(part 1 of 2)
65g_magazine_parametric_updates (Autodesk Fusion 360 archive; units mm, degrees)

design "65g_magazine_parametric_updates" references "65_g_floorplate"
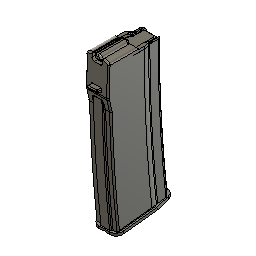
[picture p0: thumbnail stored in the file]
parameter "CartrigeOAL" = 57.9
parameter "magazineShoulder" = 35.6
parameter "feedLipRadius" = 5.6
parameter "primaryWallThickness" = 2
parameter "feedliplength" = 29.6
parameter "frontWidth" = 16
parameter "rearwidth" = 22
parameter "addtlfeedlipthickness" = 3.5
parameter "bananaFactor" = 1509
parameter "floorplateclearance" = 2
parameter "followerOffset" = -0.75
parameter "d1137" = 350
parameter "d372" = 1
parameter "d374" = 0.7
parameter "d376" = 0.7
parameter "d377" = -1
parameter "d378" = 0
parameter "d380" = 0.5
parameter "d387" = 7
parameter "d389" = 1
parameter "d390" = 4
parameter "d391" = 0.75
parameter "d392" = -9
parameter "d393" = 0
parameter "d394" = 10
parameter "d400" = 10
parameter "d401" = 5
parameter "d402" = -0.5
parameter "d403" = 0
parameter "d404" = 0
parameter "d405" = 0
parameter "d406" = 4
parameter "d407" = 3
parameter "d408" = 3
parameter "d409" = 0
parameter "d411" = 1
parameter "d412" = 17
parameter "d413" = 1.5
parameter "d415" = 3
parameter "d418" = 6
parameter "d419" = 1.5
parameter "d420" = 2.5
parameter "d421" = 0
parameter "d423" = 2
parameter "d425" = 0.5
base_feature "Base Feature1" bodies "follower", "mag body", "feed geometry", "random cube", "placeholder to establish center"
derived_base_feature "Derived Base Feature2" bodies "main body", "updated lock lug", "template lock lug from m76"
remove_body "RemoveBody1"
sketch "top down profile" plane through (0, 0, 0) normal (0, 1, 0) x axis (1, 0, 0)
  line L1 (-11, 0) -> (0, 0)
  line L2 (0, 57.9) -> (0, 0)
  line L3 (-11, 35.6) -> (-11, 0)
  line L4 (-8, 44.9274) -> (-8, 53.9)
  line L5 (-4, 57.9) -> (0, 57.9)
  line L6 (-4, 57.9) -> (0, 57.9)
  line L7 (0, 57.9) -> (0, 0)
  line L8 (11, 35.6) -> (11, 0)
  line L9 (8, 44.9274) -> (8, 53.9)
  line L10 (4, 57.9) -> (0, 57.9)
  line L11 (11, 0) -> (0, 0)
  line L12 (-13, -2) -> (0, -2)
  line L13 (-4.2574, 61.8) -> (0, 61.8)
  line L14 (-13, 37) -> (-13, -2)
  line L15 (-6.3787, 60.9213) -> (-10.1219, 57.1781)
  line L16 (6.3787, 60.9213) -> (10.1219, 57.1781)
  line L17 (13, 37) -> (13, -2)
  line L18 (13, -2) -> (0, -2)
  line L19 (4.2574, 61.8) -> (0, 61.8)
  line L20 (-11, 27.6) -> (-13, 27.6)
  line L21 (-11, -2) -> (-11, 0)
  line L22 (-9.4578, 32.9452) -> (-8.5625, 43.1785)
  line L23 (0.2269, 43.1785) -> (-8.5625, 43.1785)
  line L24 (-9.9889, 31.486) -> (-11, 30.042)
  line L25 (-11.7322, 43.1785) -> (-8.5625, 43.1785)
  line L26 (-11, 49.3) -> (-8, 49.3)
  line L27 (-30.8129, 55.0827) -> (-11, 55)
  line L28 (-30.9385, 25) -> (-30.8129, 55.0827)
  line L29 (-13, 25) -> (-30.9385, 25)
  line L30 (-11, 45.4853) -> (-11, 55)
  line L31 (11, 45.4853) -> (11, 55)
  line L32 (-6, -4) -> (6, -4)
  line L33 (6, -2) -> (6, -4)
  line L34 (-6, -2) -> (-6, -4)
  arc A1 centre (-4, 53.9) radius 4 clockwise from (-8, 53.9) to (-4, 57.9)
  arc A2 centre (2, 35.6) radius 13 clockwise from (-11, 35.6) to (-8.5625, 43.1785)
  arc A3 centre (-11, 44.9274) radius 3 clockwise from (-8, 44.9274) to (-8.5625, 43.1785)
  arc A4 centre (-2, 35.6) radius 13 clockwise from (8.5625, 43.1785) to (11, 35.6)
  arc A5 centre (11, 44.9274) radius 3 clockwise from (8.5625, 43.1785) to (8, 44.9274)
  arc A6 centre (4, 53.9) radius 4 clockwise from (4, 57.9) to (8, 53.9)
  arc A7 centre (2, 37) radius 15 clockwise from (-13, 37) to (-11.4211, 43.6989)
  arc A8 centre (-15, 45.4853) radius 4 clockwise from (-11, 45.4853) to (-11.4211, 43.6989)
  arc A9 centre (-8.0005, 55.0568) radius 3 clockwise from (-11, 55) to (-10.1219, 57.1781)
  arc A10 centre (-4.2574, 58.8) radius 3 clockwise from (-6.3787, 60.9213) to (-4.2574, 61.8)
  arc A11 centre (4.2574, 58.8) radius 3 clockwise from (4.2574, 61.8) to (6.3787, 60.9213)
  arc A12 centre (8.0005, 55.0568) radius 3 clockwise from (10.1219, 57.1781) to (11, 55)
  arc A13 centre (15, 45.4853) radius 4 clockwise from (11.4211, 43.6989) to (11, 45.4853)
  arc A14 centre (-2, 37) radius 15 clockwise from (11.4211, 43.6989) to (13, 37)
  arc A15 centre (-12.4464, 33.2067) radius 3 clockwise from (-9.4578, 32.9452) to (-9.9889, 31.486)
  circle C1 centre (-10.808, 41.9164) radius 1.2808
  point P1 (0, 0)
  point P2 (0, 0)
  point P4 (0, 0)
  point P25 (0, 0)
  point P3 (-11, 0)
  point P16 (11, 0)
  point P14 (0, 0)
  point P5 (0, 57.9)
  point P15 (0, 57.9)
  point P7 (-4, 57.9)
  point P24 (4, 57.9)
  point P8 (-8, 53.9)
  point P22 (8, 53.9)
  point P10 (-11, 35.6)
  point P17 (11, 35.6)
  point P12 (-8, 44.9274)
  point P21 (8, 44.9274)
  point P13 (-8.5625, 43.1785)
  point P19 (8.5625, 43.1785)
  point P33 (-5.5, 61.8)
  point P26 (0, -2)
  point P52 (0, -2)
  point P27 (-13, -2)
  point P51 (13, -2)
  point P28 (-13, 37)
  point P50 (13, 37)
  point P30 (-11, 45.4853)
  point P46 (11, 45.4853)
  point P31 (-11.4211, 43.6989)
  point P48 (11.4211, 43.6989)
  point P34 (-10.1219, 57.1781)
  point P43 (10.1219, 57.1781)
  point P35 (-11, 55)
  point P45 (11, 55)
  point P37 (-6.3787, 60.9213)
  point P42 (6.3787, 60.9213)
  point P38 (-4.2574, 61.8)
  point P41 (4.2574, 61.8)
  point P54 (-13, 27.6)
  point P55 (-11, 27.6)
  point P56 (-11, -2)
  point P58 (-11, 30.042)
  point P62 (-11.7322, 43.1785)
  point P63 (-8, 49.3)
  point P67 (-13, 25)
  point P70 (6, -2)
  point P71 (-6, -2)
  point P68 (6, -4)
  point P69 (-6, -4)
  point P72 (-10.808, 41.9164)
  coincident P1 P2
  horizontal L1
  coincident P1 P4
  perpendicular L1 L2
  perpendicular L1 L3
  perpendicular L1 L4
  perpendicular L2 L5
  tangent L5 A1
  tangent L4 A1
  tangent L6 A1
  tangent L3 A2
  tangent A2 A3
  tangent L4 A3
  symmetric P2 L2 P25
  symmetric P3 L2 P16
  symmetric P4 L2 P14
  symmetric P5 L2 P15
  symmetric L2 P7 P24
  symmetric L2 A1 A6
  symmetric L2 P8 P22
  symmetric L2 P10 P17
  symmetric L2 A2 A4
  symmetric L2 P12 P21
  symmetric L2 P13 P19
  symmetric L2 A3 A5
  horizontal L12
  horizontal L13
  perpendicular L12 L14
  tangent L14 A7
  tangent A7 A8
  tangent L15 A9
  coincident P33 L15
  coincident L13 P33
  tangent L15 A10
  tangent L13 A10
  equal A9 A10
  symmetric L2 P26 P52
  symmetric L2 P27 P51
  symmetric L2 P28 P50
  symmetric L2 A7 A14
  symmetric L2 P30 P46
  symmetric L2 P31 P48
  symmetric L2 A8 A13
  symmetric L2 P34 P43
  symmetric L2 P35 P45
  symmetric L2 A9 A12
  symmetric L2 P37 P42
  symmetric L2 P38 P41
  symmetric L2 A10 A11
  coincident L14 P54
  coincident L3 P55
  perpendicular L3 L20
  coincident L12 P56
  perpendicular L12 L21
  horizontal L23
  coincident L3 P58
  tangent L22 A15
  tangent L24 A15
  horizontal L25
  coincident A8 P62
  coincident L4 P63
  perpendicular L27 L28
  coincident L14 P67
  perpendicular L14 L29
  tangent A8 L30
  vertical L30
  parallel L11 L32
  coincident L18 P70
  perpendicular L18 L33
  coincident L12 P71
  perpendicular L12 L34
  tangent A2 C1
  tangent A7 C1
  dimension "d571" distance P2 P3 = 11 (= "rearwidth / 2")
  dimension "d572" distance P4 P5 = 57.9 (= "CartrigeOAL")
  dimension "d573" distance P5 L4 = 8 (= "frontWidth / 2")
  dimension "d574" diameter A1 = 8
  dimension "d577" diameter A3 = 6
  dimension "d578" distance P26 P27 = 13 (= "d571 + 2 mm")
  dimension "d579" distance L1 L12 = 2 (= "primaryWallThickness")
  dimension "d580" distance L12 L13 = 63.8 (= "d572 + 5.9 mm")
  dimension "d586" radius A8 = 4
  dimension "d590" radius A9 = 3
  dimension "d591" angle L13 L15 = 135
  dimension "d601" distance L12 L20 = 29.6 (= "feedliplength")
  dimension "d618" angle L22 L23 = 95
  dimension "d622" radius A15 = 3
  dimension "d623" angle L3 L24 = 145
  dimension "d679" distance L13 L26 = 12.5
  dimension "d681" distance L13 P35 = 6.8
  dimension "d683" distance L3 L14 = 2 (= "d579")
  dimension "d685" distance P3 P10 = 35.6 (= "magazineShoulder")
  dimension "d686" distance L1 P28 = 37 (= "d685 + 1.4 mm")
  dimension "d699" distance P58 L25 = 13.1365
  dimension "d700" distance L7 L30 = 11 (= "d573 + 3 mm")
  dimension "d754" distance P68 P69 = 12
  dimension "d755" distance L7 P68 = 6 (= "d754 / 2")
  dimension "d756" distance L18 L32 = 2
  dimension "d779" diameter C1 = 2.5616
  dimension "d780" distance P30 P72 = 3.5688
sketch "Sketch4" plane through (0, 0, 0) normal (0, 1, 0) x axis (1, 0, 0)
  line L1 (2.35, 53.733) -> (2.35, 46.32)
  line L2 (2.35, 53.733) -> (2.35, 52.4025)
  line L3 (2.35, 48.3729) -> (2.35, 52.4025)
  line L4 (2.35, 45) -> (2.35, 48.3729)
  line L5 (2.35, 46.32) -> (2.35, 45)
  curve K1 (1.7875, 44.5687) -> (-0.65, 36.9798)
  line L6 (1.7875, 44.5687) -> (1.7875, 43.2511)
  line L7 (-0.65, 36.9798) -> (-0.65, 35.6726)
  line L8 (-0.65, 36.9798) -> (-0.65, 1.2627)
  line L9 (-0.65, 36.9798) -> (-0.65, 35.6726)
  line L10 (-0.65, 29.2298) -> (-0.65, 35.6726)
  line L11 (-0.65, 0.0025) -> (-0.65, 29.2298)
  line L12 (-0.65, 0.0025) -> (-0.65, 1.2627)
  curve K2 (2.35, 46.32) -> (1.7875, 44.5687)
  line L13 (2.35, 46.32) -> (2.35, 45)
  line L14 (1.7875, 44.5687) -> (1.7875, 43.2511)
  line L15 (0.8031, 31.5304) -> (1.7875, 43.2511)
  line L16 (-0.65, 29.2298) -> (0.3422, 30.4123)
  arc A1 centre (-1.1899, 31.6978) radius 2 clockwise from (0.8031, 31.5304) to (0.3422, 30.4123)
sketch "Banana Factor" plane through (0, 0, 0) normal (1, 0, 0) x axis (0, 1, 0)
  line L1 (0, -57.9) -> (0, 0)
  line L2 (0, -35.6) -> (0, 0)
  line L3 (0, -35.6) -> (0, -43.1785)
  line L4 (0, -43.1785) -> (0, -44.9274)
  line L5 (0, -44.9274) -> (0, -53.9)
  line L6 (0, -53.9) -> (0, -57.9)
  line L7 (0, -57.9) -> (0, 0)
  line L8 (0, -35.6) -> (0, 0)
  line L9 (0, -35.6) -> (0, -43.1785)
  line L10 (0, -43.1785) -> (0, -44.9274)
  line L11 (0, -44.9274) -> (0, -53.9)
  line L12 (0, -53.9) -> (0, -57.9)
  line L13 (0, -29.227) -> (0, 0)
  line L14 (0, -1538.227) -> (0, -29.227)
  circle C1 centre (0, -1538.227) radius 1509
  point P12 (0, 0)
  point P22 (0, 0)
  point P24 (0, -1538.227)
  point P25 (0, -1538.227)
  point P23 (0, -29.227)
  coincident P12 P22
  parallel L2 L13
  parallel L5 L14
  coincident P24 P25
  coincident P23 C1
  dimension "d593" distance P22 P23 = 29.227
  dimension "d594" distance P23 P24 = 1509 (= "bananaFactor")
sweep "Sweep1" sketch "top down profile" TwistAngle 0 TaperAngle 0
sketch "feed lip curvature/radius" plane through (0, 0, 0) normal (0, 0, 1) x axis (1, 0, 0)
  line L1 (-5.4, 0) -> (-11, 0)
  line L2 (-5.4, 5.6) -> (-5.4, 0)
  curve K1 (0.2, 3.5) -> (-11, 3.5)
  curve K2 (-5.4, 5.5588) -> (-5.4, 1.4412)
  curve K3 (-5.4, 6.6) -> (-5.4, -6.6)
  curve K4 (-11, 0) -> (0.2, 0)
  line L3 (0.7, 0) -> (-5.4, 0)
  circle C1 centre (-5.4, 0) radius 5.6
  closed curve K5 centre (-5.4, 3.5)
  closed curve K6 centre (-5.4, 0)
  point P2 (-11, 0)
  point P3 (-11, 0)
  point P4 (-5.4, 0)
  point P5 (-5.4, 0)
  point P6 (-5.4, 5.6)
  point P8 (-11, 3.5)
  point P9 (0.2, 3.5)
  point P10 (-5.4, 1.4412)
  point P11 (-5.4, 5.5588)
  point P13 (-5.4, -6.6)
  point P14 (-5.4, 6.6)
  point P15 (0.2, 0)
  point P16 (-11, 0)
  point P7 (-5.4, 3.5)
  coincident P2 P3
  horizontal L1
  coincident P4 P5
  coincident P2 C1
  coincident C1 P6
  perpendicular L1 L2
  coincident K5 P8
  coincident K5 P9
  coincident K5 P10
  coincident K5 P11
  horizontal K1
  collinear L2 K2
  coincident L2 P11
  coincident K6 P13
  coincident K6 P14
  coincident K6 P15
  coincident K6 P16
  concentric C1 K6
  coincident P3 P16
  horizontal L3
  dimension "d602" distance P3 P4 = 5.6 (= "feedLipRadius")
  dimension "d730" distance K5 = 11.2 (= "feedLipRadius * 2")
  dimension "d731" distance P5 K1 = 3.5 (= "addtlfeedlipthickness")
  dimension "d746" = 4.1176 (= "d747 * 2 / 1.02")
  dimension "d747" distance P6 P7 = 2.1
  dimension "d1105" distance K6 = 13.2
sweep "Sweep2" sketch "top down profile" TwistAngle 0 TaperAngle 0 bodies "feed lip"
extrude "Extrude2" new body sketch "top down profile" profile of L3 L12 L14 L20 L21 along normal blind 3.5 (= "addtlfeedlipthickness")
sweep "Sweep1" TwistAngle 0 TaperAngle -0.8
extrude "Extrude9" new body sketch "top down profile" profile of L3 L12 L14 L20 L21 along normal blind 3.5 (= "addtlfeedlipthickness")
sweep "Sweep5" TwistAngle 0 TaperAngle 0
move "Move1"
extrude "Extrude17" cut sketch "feed lip curvature/radius" profile of C1 K5 K6 to an object Side2Offset 0
sketch "feed lip fill in" plane through (0, 0, 2) normal (0, 0, 1) x axis (1, 0, 0)
  line L1 (-11, 0) -> (-13, 0)
  line L2 (-6.3525, 7.5401) -> (-6.2247, 6.528)
  line L3 (-6.2247, 0) -> (-6.2247, 6.528)
  line L4 (-13, 0) -> (0, 0)
  line L5 (-13, 0) -> (-13, 3.5)
  line L6 (-6.575, 7.5184) -> (-6.5744, 7.5087)
  curve K1 (-6.575, 7.5184) -> (-13, 3.5)
  line L7 (-6.5751, 12.5087) -> (-6.5744, 7.5087)
  line L8 (-18, 0) -> (-13, 0)
  line L9 (-18, 12.7693) -> (-18, 0)
  line L10 (-6.5751, 12.5087) -> (-18, 12.7693)
  arc A1 centre (-5.4, 0) radius 7.6 clockwise from (-6.5744, 7.5087) to (-6.3525, 7.5401)
  closed curve K2 centre (-5.4, 0)
  point P4 (-6.2247, 6.528)
  point P7 (-6.2247, 6.528)
  point P8 (-6.2247, 0)
  point P2 (-6.5744, 7.5087)
  point P14 (-6.5744, 7.5087)
  point P11 (-13, 0)
  point P16 (-13, 0)
  point P15 (-6.5751, 12.5087)
  point P17 (-18, 0)
  coincident P4 P7
  coincident P8 L4
  perpendicular L3 L4
  coincident P2 P14
  coincident P11 P16
  perpendicular L5 L8
  perpendicular L8 L9
  dimension "d1089" distance P14 P15 = 5
  dimension "d1090" distance P16 P17 = 5
extrude "Extrude1" add sketch "feed lip fill in" profile of L4 L3 against normal blind 2
sketch "Draft pull tool" plane through (0, 0, 0) normal (0, 0, 1) x axis (1, 0, 0)
  line L1 (-6.2247, 6.528) -> (-6.3525, 7.5401)
  line L2 (-14.3525, 7.5401) -> (-6.3525, 7.5401)
  line L3 (-14.3525, 6.5401) -> (-14.3525, 7.5401)
  line L4 (-6.3525, 6.5401) -> (-14.3525, 6.5401)
  line L5 (-6.3525, 7.5401) -> (-6.3525, 6.5401)
  arc A1 centre (-5.4, 0) radius 7.6 clockwise from (-6.5744, 7.5087) to (-6.3525, 7.5401)
  point P2 (-6.3525, 7.5401)
  point P6 (-6.3525, 7.5401)
  point P7 (-14.3525, 7.5401)
  point P9 (-6.3525, 6.5401)
  horizontal L2
  vertical L3
  horizontal L4
  vertical L5
  coincident P2 P6
  dimension "d612" distance P6 P7 = 8
  dimension "d613" distance P6 P9 = 1
extrude "Extrude2" new body sketch "Draft pull tool" against normal blind 25 bodies "draft tool"
extrude "Extrude3" new body sketch "top down profile" profile of L3 L4 A2 A3 L14 A7 A8 L20 L22 L24 A15 L25 L26 along normal blind 3
draft "Draft2" Angle1 -45 Angle2 0
combine "Combine1"
sweep "Sweep3" sketch "top down profile" TwistAngle 0 TaperAngle 0
sweep "Sweep4" sketch "top down profile" TwistAngle 0 TaperAngle 0
sketch "cut draft angle between feed lips" plane through (0, 0, 0) normal (1, 0, 0) x axis (0, 1, 0)
  line L1 (3.8726, -39.715) -> (0, -49.3)
  line L2 (7, -39.715) -> (3.8726, -39.715)
  line L3 (7, -69.3) -> (7, -39.715)
  line L4 (0, -69.3) -> (7, -69.3)
  line L5 (0, -49.3) -> (0, -69.3)
  line L6 (0, 2) -> (0, -37)
  line L7 (-163.9995, -45.9848) -> (-168.26, -7.2183)
  line L8 (0, -57.9) -> (0, 0)
  arc A1 centre (0, -1538.227) radius 1540.227 clockwise from (-168.26, -7.2183) to (0, 2)
  arc A2 centre (0, -1538.227) radius 1501.227 clockwise from (-163.9995, -45.9848) to (0, -37)
  point P4 (7, -69.3)
  point P5 (0, -69.3)
  point P2 (3.8726, -39.715)
  point P13 (0, -49.3)
  point P3 (7, -39.715)
  point P6 (0, -49.3)
  point P12 (0, 2)
  perpendicular L2 L3
  perpendicular L3 L4
  vertical L3
  vertical L5
  dimension "d691" distance P4 P5 = 7
  dimension "d694" distance P2 P13 = 10.3377
  dimension "d695" angle L1 L8 = 158
  dimension "d696" distance P2 P3 = 3.1274
  dimension "d697" distance P6 P12 = 51.3 (= "magazineShoulder + primaryWallThickness + 13.7 mm")
  dimension "d698" distance P5 P6 = 20
extrude "Extrude1" cut sketch "cut draft angle between feed lips" profile of L1 L2 L3 L4 L5 against normal blind 13.5
combine "Combine2"
fillet "Fillet2" radius 1
mirror "Mirror1" mirrorStitchTolerance 0.1 bodies "feed lip (1)"
sketch "Sketch6" plane through (0, 0, 0) normal (0, 0, 1) x axis (1, 0, 0)
sketch "cut front clearance for rounds" plane through (0, 0, 0) normal (0, 0, 1) x axis (1, 0, 0)
  line L1 (-8, -3.1) -> (-8, 0)
  line L2 (8, -3.1) -> (8, 0)
  line L3 (-8, -3.1) -> (8, -3.1)
  line L4 (8, 0) -> (-8, 0)
  circle C1 centre (4.9, 0) radius 3.1
  circle C2 centre (-4.9, 0) radius 3.1
  point P3 (-8, 0)
  point P4 (-8, 0)
  point P2 (8, 0)
  point P6 (8, 0)
  point P5 (-8, -3.1)
  point P7 (8, -3.1)
  coincident P3 P4
  vertical L1
  coincident P2 P6
  vertical L2
  tangent L2 C1
  tangent L3 C1
  tangent L1 C2
  tangent L3 C2
  dimension "d656" distance P4 P5 = 3.1
  dimension "d657" distance P6 P7 = 3.1
  dimension "d659" diameter C1 = 6.2 (= "d657 * 2")
  dimension "d660" diameter C2 = 6.2 (= "d659")
move "Move3"
sketch "Sketch7" plane through (0, 0, 0) normal (0, 0, 1) x axis (1, 0, 0)
sketch "locking lug profile" plane through (0, 0, 0) normal (1, 0, 0) x axis (0, 1, 0)
  line L1 (-20.5632, -63.0982) -> (-16.5, -59.6888)
  line L2 (-10.0812, -59.6888) -> (-16.5, -59.6888)
  line L3 (1.3778, -59.6) -> (-3.1, -59.6)
  line L4 (-6.0779, -62.5779) -> (-3.1, -59.6)
  line L5 (2.907, -59.6) -> (-3.1, -59.6)
  line L6 (-7.9604, -62.5779) -> (-9.5957, -59.6279)
  line L7 (-3.8651, -59.6279) -> (-9.5957, -59.6279)
  line L8 (-6.0779, -62.5779) -> (-7.9604, -62.5779)
  line L9 (-20.5632, -69) -> (-20.5632, -63.0982)
  line L10 (1.3778, -69) -> (-20.5632, -69)
  line L11 (1.3778, -69) -> (1.3778, -59.6)
  line L12 (0, -55) -> (0, -57.1781)
  line L13 (0, -60.9213) -> (0, -57.1781)
  line L14 (0, -60.9213) -> (0, -61.8)
  line L15 (-10.0805, -58.7533) -> (-9.5957, -59.6279)
  line L16 (-2.2533, -58.7533) -> (-3.1, -59.6)
  line L17 (-10.0805, -58.7533) -> (-2.2533, -58.7533)
  line L18 (0, 2) -> (0, -37)
  line L19 (-163.9995, -45.9848) -> (-168.26, -7.2183)
  line L20 (1.3778, -51) -> (1.3778, -59.6)
  arc A1 centre (0.0013, -1538.227) radius 1478.6303 clockwise from (-16.5, -59.6888) to (-3.1, -59.6)
  arc A2 centre (0, -1538.227) radius 1540.227 clockwise from (-168.26, -7.2183) to (0, 2)
  arc A3 centre (0, -1538.227) radius 1501.227 clockwise from (-163.9995, -45.9848) to (0, -37)
  point P9 (-9.5957, -59.6279)
  point P19 (-3.1, -59.6)
  point P23 (0, 2)
  point P21 (-2.2533, -58.7533)
  point P20 (-10.0805, -58.7533)
  point P13 (-20.5632, -69)
  point P14 (1.3778, -69)
  point P4 (-16.5, -59.6888)
  point P5 (-20.5632, -63.0982)
  horizontal L2
  horizontal L3
  horizontal L5
  horizontal L7
  coincident A1 P9
  vertical L9
  perpendicular L9 L10
  perpendicular L10 L11
  coincident A1 P19
  parallel L6 L15
  collinear L4 L16
  horizontal L17
  perpendicular L3 L20
  dimension "d665" angle L1 L2 = 140
  dimension "d666" angle L4 L5 = 135
  dimension "d667" angle L6 L7 = 61
  dimension "d701" distance L3 P23 = 61.6 (= "CartrigeOAL + 3.7 mm")
  dimension "d702" distance L5 L17 = 0.8467
  dimension "d704" distance P21 L20 = 3.6311
  dimension "d705" distance P20 P21 = 7.8272
  dimension "d706" distance P13 P14 = 21.941
  dimension "d707" distance P4 P5 = 5.3041
extrude "Extrude6" cut sketch "locking lug profile" profile of A1 L1 L3 L4 L6 L8 L9 L10 L11 distance 11
extrude "Extrude7" new body sketch "locking lug profile" profile of A1 L4 L6 L8 L15 L17 distance 5.2
draft "Draft3" Angle1 30 Angle2 0
extrude "Extrude8" cut sketch "cut front clearance for rounds" profile of L3 C1 C2 L4 against normal blind 69.48 (magnitude of "CartrigeOAL * -1.2")
combine "Combine3" bodies "feed lip (1)", "feed lip"
fillet "Fillet12" radius 1
fillet "Fillet6" radius 2
fillet "Fillet7" radius 2.75
fillet "Fillet8" radius 1
fillet "Fillet9" radius 1
sketch "Rear locking lug profile" plane through (0, 0, 0) normal (1, 0, 0) x axis (0, 1, 0)
  line L1 (0, -37) -> (0, 2)
  line L2 (-18.7, 4.4) -> (0, 2)
  line L3 (-29.7, 4.7) -> (-18.7, 4.4)
  line L4 (-44.05, 1.37) -> (-29.7, 4.7)
  line L5 (0, 23) -> (0, 2)
  line L6 (-21.7, 0.8) -> (-21.7, 4.4818)
  line L7 (-26.4, 0.8) -> (-21.7, 0.8)
  line L8 (-26.4, 4.61) -> (-26.4, 0.8)
  line L9 (-21.7, 10.2818) -> (-21.7, 4.4818)
  line L10 (-24.5, 9.9009) -> (-21.7, 10.2818)
  line L11 (-26.4, 4.61) -> (-24.5, 9.9009)
  line L12 (7.5184, 2) -> (3.5, 2)
  line L13 (6.0649, 3.7246) -> (-18.7, 4.4)
  line L14 (7.5235, 2.1843) -> (7.5184, 2)
  line L15 (0, 2) -> (7.5184, 2)
  arc A1 centre (0, -1538.227) radius 1540.227 clockwise from (-168.26, -7.2183) to (0, 2)
  arc A2 centre (6.024, 2.2252) radius 1.5 clockwise from (6.0649, 3.7246) to (7.5235, 2.1843)
  point P2 (0, 2)
  point P4 (0, 2)
  point P7 (-44.05, 1.37)
  point P8 (0, 2)
  point P11 (0, 2)
  point P13 (-21.7, 4.4818)
  point P16 (-26.4, 4.61)
  point P20 (7.5184, 2)
  point P21 (7.5184, 2)
  point P5 (-18.7, 4.4)
  point P6 (-29.7, 4.7)
  point P14 (-21.7, 0.8)
  point P15 (-26.4, 0.8)
  point P17 (-21.7, 10.2818)
  point P18 (-24.5, 9.9009)
  coincident P2 P4
  coincident P7 A1
  coincident P8 P11
  vertical L5
  coincident L3 P13
  vertical L6
  perpendicular L6 L7
  coincident L3 P16
  perpendicular L7 L8
  parallel L6 L9
  parallel L3 L13
  coincident P20 P21
  perpendicular L13 L14
  tangent L14 A2
  tangent L13 A2
  dimension "d766" distance P4 P5 = 18.7
  dimension "d767" distance P4 P6 = 29.7
  dimension "d768" distance P7 P11 = 44.05
  dimension "d769" distance P5 P11 = 2.4
  dimension "d770" distance P6 P11 = 2.7
  dimension "d771" distance P11 P14 = 1.2
  dimension "d772" distance P11 P13 = 21.7
  dimension "d773" distance P14 P15 = 4.7
  dimension "d1081" distance P13 P17 = 5.8
  dimension "d1088" radius A2 = 1.5
  dimension "d1100" angle L10 L11 = 117.5
  dimension "d1101" distance P17 P18 = 2.8
sketch "recut back profile after reinforcement" plane through (0, 0, 2) normal (0, 0, 1) x axis (1, 0, 0)
  line L1 (6.2247, 6.528) -> (6.2731, 6.911)
  line L2 (6.2247, 2.75) -> (6.2247, 6.528)
  line L3 (13, 0) -> (3.4747, 0)
  line L4 (13, 3.5) -> (13, 0)
  curve K1 (6.575, 7.5184) -> (13, 3.5)
  line L5 (6.5744, 7.5087) -> (6.575, 7.5184)
  line L6 (-6.575, 7.5184) -> (-6.5744, 7.5087)
  curve K2 (-6.575, 7.5184) -> (-13, 3.5)
  line L7 (-13, 0) -> (-13, 3.5)
  line L8 (-3.4747, 0) -> (-13, 0)
  line L9 (-6.2247, 6.528) -> (-6.2247, 2.75)
  line L10 (-6.2731, 6.911) -> (-6.2247, 6.528)
  line L11 (3.4747, 0) -> (-3.4747, 0)
  line L12 (16, 0) -> (13, 0)
  line L13 (16, 15) -> (16, 0)
  line L14 (-16, 0) -> (-13, 0)
  line L15 (-16, 15) -> (-16, 0)
  line L16 (16, 15) -> (-16, 15)
  arc A1 centre (7.2652, 6.7857) radius 1 clockwise from (6.2731, 6.911) to (6.5744, 7.5087)
  arc A2 centre (3.4747, 2.75) radius 2.75 clockwise from (6.2247, 2.75) to (3.4747, 0)
  arc A3 centre (-7.2652, 6.7857) radius 1 clockwise from (-6.5744, 7.5087) to (-6.2731, 6.911)
  arc A4 centre (-3.4747, 2.75) radius 2.75 clockwise from (-3.4747, 0) to (-6.2247, 2.75)
  point P18 (-3.4747, 0)
  point P22 (-3.4747, 0)
  point P7 (3.4747, 0)
  point P23 (3.4747, 0)
  point P9 (13, 0)
  point P24 (13, 0)
  point P17 (-13, 0)
  point P27 (-13, 0)
  point P25 (16, 0)
  point P26 (16, 15)
  point P28 (-16, 0)
  point P29 (-16, 15)
  coincident P18 P22
  coincident P7 P23
  coincident P9 P24
  perpendicular L4 L12
  perpendicular L12 L13
  coincident P17 P27
  perpendicular L7 L14
  perpendicular L14 L15
  dimension "d1093" distance P24 P25 = 3
  dimension "d1094" distance P25 P26 = 15
  dimension "d1095" distance P27 P28 = 3
  dimension "d1096" distance P28 P29 = 15
extrude "Extrude10" add sketch "Rear locking lug profile" profile of L2 L3 L4 A1 L6 L8 L12 L13 L14 A2 L15 distance 13
extrude "Extrude16" cut sketch "recut back profile after reinforcement" profile of A1 L1 L2 A2 L4 K1 L5 A3 L6 K2 L7 A4 L9 L10 L11 L12 L13 L14 L15 L16 along normal blind 6
sweep "Sweep6" sketch "top down profile" TwistAngle 0 TaperAngle 0
chamfer "Chamfer1" distance 15 distance 2
combine "Combine4"
extrude "Extrude3" cut sketch "Rear locking lug profile" profile of L3 A1 L6 L7 L8 distance 5.8
extrude "Extrude15" new body sketch "Rear locking lug profile" profile of L3 A1 L6 L7 L8 L9 L10 L11 distance 5.7 bodies "updated locking lug"
offset_faces "OffsetFaces1" distance -0.07
offset_faces "OffsetFaces2" distance -0.07
fillet "Fillet13" radius 1.5
fillet "Fillet15" radius 1
fillet "Fillet10" radius 1 7.5
fillet "Fillet11" radius 1
move "Move4"
move "Move5"
sketch "CutBasePlateClearance" plane through (0, -167.0358, -18.3575) normal (0, -0.994, -0.1092) x axis (-1, 0, 0)
  line L1 (-10, -9.2063) -> (10, -9.2063)
  line L2 (-11, 26.3937) -> (-11, -8.2063)
  line L3 (-8, 44.6937) -> (-8, 35.7211)
  line L4 (4, 48.6937) -> (-4, 48.6937)
  line L5 (8, 35.7211) -> (8, 44.6937)
  line L6 (11, -8.2063) -> (11, 26.3937)
  line L7 (13, 27.7937) -> (13, -9.7063)
  line L8 (6.3787, 51.715) -> (10.1219, 47.9719)
  line L9 (-4.2574, 52.5937) -> (4.2574, 52.5937)
  line L10 (-10.1219, 47.9719) -> (-6.3787, 51.715)
  line L11 (-13, -9.7063) -> (-13, 27.7937)
  line L12 (11.5, -11.2063) -> (7, -11.2063)
  line L13 (5, -13.2063) -> (-5, -13.2063)
  line L14 (0, 52.5937) -> (0, -13.2063)
  line L15 (-12.3, 52.5937) -> (-12.3, -13.2063)
  line L16 (12.3, 52.5937) -> (12.3, -13.2063)
  line L17 (-30, -13.2063) -> (30, -13.2063)
  line L18 (-30, 52.5937) -> (30, 52.5937)
  line L19 (-15.3, 52.5937) -> (-15.3, -13.2063)
  line L20 (15.3, 52.5937) -> (15.3, -13.2063)
  line L21 (11, 45.7937) -> (11, 36.279)
  line L22 (-11, 36.279) -> (-11, 45.7937)
  line L23 (-7, -11.2063) -> (-11.5, -11.2063)
  arc A1 centre (-10, -8.2063) radius 1 clockwise from (-10, -9.2063) to (-11, -8.2063)
  arc A2 centre (2, 26.3937) radius 13 clockwise from (-11, 26.3937) to (-8.5625, 33.9722)
  arc A3 centre (-11, 35.7211) radius 3 clockwise from (-8, 35.7211) to (-8.5625, 33.9722)
  arc A4 centre (-4, 44.6937) radius 4 clockwise from (-8, 44.6937) to (-4, 48.6937)
  arc A5 centre (4, 44.6937) radius 4 clockwise from (4, 48.6937) to (8, 44.6937)
  arc A6 centre (11, 35.7211) radius 3 clockwise from (8.5625, 33.9722) to (8, 35.7211)
  arc A7 centre (-2, 26.3937) radius 13 clockwise from (8.5625, 33.9722) to (11, 26.3937)
  arc A8 centre (10, -8.2063) radius 1 clockwise from (11, -8.2063) to (10, -9.2063)
  arc A9 centre (4.2574, 49.5937) radius 3 clockwise from (4.2574, 52.5937) to (6.3787, 51.715)
  arc A10 centre (-4.2574, 49.5937) radius 3 clockwise from (-6.3787, 51.715) to (-4.2574, 52.5937)
  arc A11 centre (11.5, -9.7063) radius 1.5 clockwise from (13, -9.7063) to (11.5, -11.2063)
  arc A12 centre (-2, 27.7937) radius 15 clockwise from (11.4211, 34.4926) to (13, 27.7937)
  arc A13 centre (15, 36.279) radius 4 clockwise from (11.4211, 34.4926) to (11, 36.279)
  arc A14 centre (8.0005, 45.8505) radius 3 clockwise from (10.1219, 47.9719) to (11, 45.7937)
  arc A15 centre (-8.0005, 45.8505) radius 3 clockwise from (-11, 45.7937) to (-10.1219, 47.9719)
  arc A16 centre (-15, 36.279) radius 4 clockwise from (-11, 36.279) to (-11.4211, 34.4926)
  arc A17 centre (2, 27.7937) radius 15 clockwise from (-13, 27.7937) to (-11.4211, 34.4926)
  arc A18 centre (-11.5, -9.7063) radius 1.5 clockwise from (-11.5, -11.2063) to (-13, -9.7063)
  arc A19 centre (5, -12.2063) radius 1 clockwise from (6, -12.2063) to (5, -13.2063)
  arc A20 centre (7, -12.2063) radius 1 clockwise from (6, -12.2063) to (7, -11.2063)
  arc A21 centre (-7, -12.2063) radius 1 clockwise from (-7, -11.2063) to (-6, -12.2063)
  arc A22 centre (-5, -12.2063) radius 1 clockwise from (-5, -13.2063) to (-6, -12.2063)
  point P40 (0, -13.2063)
  point P41 (0, 52.5937)
  point P42 (-12.3, -13.2063)
  point P44 (12.3, -13.2063)
  point P45 (12.3, 52.5937)
  point P43 (-12.3, 52.5937)
  point P46 (30, -13.2063)
  point P47 (-30, -13.2063)
  midpoint L13 P40
  midpoint L9 P41
  vertical L15
  vertical L16
  horizontal L17
  coincident P40 L17
  coincident P42 L17
  coincident P44 L17
  dimension "d801" distance P40 P41 = 65.8
  dimension "d802" distance P44 P45 = 65.8 (= "d801")
  dimension "d803" distance P42 P43 = 65.8 (= "d801")
  dimension "d804" distance L15 L16 = 24.6
  dimension "d805" distance L14 L15 = 12.3 (= "d804 / 2")
  dimension "d806" distance P46 P47 = 60
  dimension "d807" distance P40 P47 = 30 (= "d806 / 2")
  dimension "d808" = 65.8
  dimension "d809" = -3
  dimension "d810" = 3
extrude "Extrude12" cut sketch "CutBasePlateClearance" profile of L7 L11 L15 L16 L17 L18 L19 L20 against normal blind 2 (magnitude of "-1 * ( floorplateclearance )")
draft "Draft4" Angle1 50 Angle2 0
draft "Draft5" Angle1 50 Angle2 0
sketch "Sketch8" plane through (0, -167.0358, -18.3575) normal (0, -0.994, -0.1092) x axis (-1, 0, 0)
sketch "addLipForBasePlate" plane through (0, -167.0358, -18.3575) normal (0, -0.994, -0.1092) x axis (-1, 0, 0)
  line L1 (6.2, -14.5063) -> (-6.2, -14.5063)
  line L2 (-14.2, -6.5063) -> (-14.2, 32.2937)
  line L3 (14.2, -6.5063) -> (14.2, 32.2937)
  line L4 (0, 52.5937) -> (0, -13.2063)
  line L5 (4.4118, 54.4937) -> (-4.4118, 54.4937)
  line L6 (-10, -9.2063) -> (10, -9.2063)
  line L7 (11.3055, 48.7093) -> (14.2, 32.2937)
  line L8 (-11.3055, 48.7093) -> (-14.2, 32.2937)
  line L9 (12.3, 32.3225) -> (12.3, -10.9751)
  line L10 (11, 45.7937) -> (11, 36.279)
  line L11 (6.3787, 51.715) -> (10.1219, 47.9719)
  line L12 (-4.2574, 52.5937) -> (4.2574, 52.5937)
  line L13 (-10.1219, 47.9719) -> (-6.3787, 51.715)
  line L14 (-11, 36.279) -> (-11, 45.7937)
  line L15 (-12.3, -10.9751) -> (-12.3, 32.3225)
  line L16 (-7, -11.2063) -> (-11.5, -11.2063)
  line L17 (5, -13.2063) -> (-5, -13.2063)
  line L18 (11.5, -11.2063) -> (7, -11.2063)
  line L19 (-10, -9.2063) -> (10, -9.2063)
  line L20 (-11, 26.3937) -> (-11, -8.2063)
  line L21 (-8, 44.6937) -> (-8, 35.7211)
  line L22 (4, 48.6937) -> (-4, 48.6937)
  line L23 (8, 35.7211) -> (8, 44.6937)
  line L24 (11, -8.2063) -> (11, 26.3937)
  arc A1 centre (4.4118, 47.4937) radius 7 clockwise from (4.4118, 54.4937) to (11.3055, 48.7093)
  arc A2 centre (-4.4118, 47.4937) radius 7 clockwise from (-11.3055, 48.7093) to (-4.4118, 54.4937)
  arc A3 centre (6.2, -6.5063) radius 8 clockwise from (14.2, -6.5063) to (6.2, -14.5063)
  arc A4 centre (-6.2, -6.5063) radius 8 clockwise from (-6.2, -14.5063) to (-14.2, -6.5063)
  arc A5 centre (-2, 27.7937) radius 15 clockwise from (11.4211, 34.4926) to (12.3, 32.3225)
  arc A6 centre (15, 36.279) radius 4 clockwise from (11.4211, 34.4926) to (11, 36.279)
  arc A7 centre (8.0005, 45.8505) radius 3 clockwise from (10.1219, 47.9719) to (11, 45.7937)
  arc A8 centre (4.2574, 49.5937) radius 3 clockwise from (4.2574, 52.5937) to (6.3787, 51.715)
  arc A9 centre (-4.2574, 49.5937) radius 3 clockwise from (-6.3787, 51.715) to (-4.2574, 52.5937)
  arc A10 centre (-8.0005, 45.8505) radius 3 clockwise from (-11, 45.7937) to (-10.1219, 47.9719)
  arc A11 centre (-15, 36.279) radius 4 clockwise from (-11, 36.279) to (-11.4211, 34.4926)
  arc A12 centre (2, 27.7937) radius 15 clockwise from (-12.3, 32.3225) to (-11.4211, 34.4926)
  arc A13 centre (-11.5, -9.7063) radius 1.5 clockwise from (-11.5, -11.2063) to (-12.3, -10.9751)
  arc A14 centre (-7, -12.2063) radius 1 clockwise from (-7, -11.2063) to (-6, -12.2063)
  arc A15 centre (-5, -12.2063) radius 1 clockwise from (-5, -13.2063) to (-6, -12.2063)
  arc A16 centre (5, -12.2063) radius 1 clockwise from (6, -12.2063) to (5, -13.2063)
  arc A17 centre (7, -12.2063) radius 1 clockwise from (6, -12.2063) to (7, -11.2063)
  arc A18 centre (11.5, -9.7063) radius 1.5 clockwise from (12.3, -10.9751) to (11.5, -11.2063)
  arc A19 centre (-10, -8.2063) radius 1 clockwise from (-10, -9.2063) to (-11, -8.2063)
  arc A20 centre (2, 26.3937) radius 13 clockwise from (-11, 26.3937) to (-8.5625, 33.9722)
  arc A21 centre (-11, 35.7211) radius 3 clockwise from (-8, 35.7211) to (-8.5625, 33.9722)
  arc A22 centre (-4, 44.6937) radius 4 clockwise from (-8, 44.6937) to (-4, 48.6937)
  arc A23 centre (4, 44.6937) radius 4 clockwise from (4, 48.6937) to (8, 44.6937)
  arc A24 centre (11, 35.7211) radius 3 clockwise from (8.5625, 33.9722) to (8, 35.7211)
  arc A25 centre (-2, 26.3937) radius 13 clockwise from (8.5625, 33.9722) to (11, 26.3937)
  arc A26 centre (10, -8.2063) radius 1 clockwise from (11, -8.2063) to (10, -9.2063)
  point P5 (14.2, 32.2937)
  point P10 (-14.2, 32.2937)
  point P3 (14.2, -14.5063)
  point P2 (-14.2, -14.5063)
  point P4 (-14.2, 32.2937)
  horizontal L1
  vertical L2
  vertical L3
  horizontal L5
  symmetric P5 L4 P10
  tangent L5 A1
  tangent L7 A1
  tangent L8 A2
  tangent L5 A2
  equal A1 A2
  coincident P3 L1
  tangent L3 A3
  tangent L1 A3
  coincident P2 L1
  tangent L2 A4
  tangent L1 A4
  equal A3 A4
  dimension "d818" distance L2 L3 = 28.4
  dimension "d819" distance L3 L4 = 14.2 (= "d818 / 2")
  dimension "d820" distance L1 L5 = 69
  dimension "d821" distance P2 P3 = 28.4 (= "d818")
  dimension "d822" distance P3 L4 = 14.2 (= "d821 / 2")
  dimension "d823" distance P2 P4 = 46.8
  dimension "d824" distance P3 P5 = 46.8 (= "d823")
  dimension "d825" distance L1 L6 = 5.3
  dimension "d826" angle L3 L7 = 170
  dimension "d827" radius A1 = 7
  dimension "d828" radius A3 = 8
  dimension "d831" distance L5 L12 = 1.9
  dimension "d832" distance L1 L17 = 1.3
extrude "Extrude13" add sketch "addLipForBasePlate" along normal blind 3
sketch "Sketch9" plane through (0, -1.6113, 14.6963) normal (0, -0.109, 0.994) x axis (1, 0, 0)
  curve K1 (2.0685, -171.2612) -> (-1.9315, -171.2612)
  line L1 (6.2685, -171.2612) -> (2.0685, -171.2612)
  line L2 (6.2685, -168.2612) -> (6.2685, -171.2612)
  line L3 (-6.1315, -168.2612) -> (6.2685, -168.2612)
  line L4 (-6.1315, -171.2612) -> (-6.1315, -168.2612)
  line L5 (-1.9315, -171.2612) -> (-6.1315, -171.2612)
  line L6 (3.0065, -170.5006) -> (-2.7534, -170.5006)
  curve K2 (2.0685, -171.2612) -> (-1.9315, -171.2612)
  horizontal L6
sketch "floor plate retainer cut" plane through (0, -1.5847, 14.4195) normal (0, -0.1092, 0.994) x axis (1, 0, 0)
  line L1 (-6.2, -168.0415) -> (6.2, -168.0415)
  line L2 (-6.2, -171.0415) -> (-6.2, -168.0415)
  line L3 (6.2, -171.0415) -> (-6.2, -171.0415)
  line L4 (6.2, -168.0415) -> (6.2, -171.0415)
  line L5 (3.7106, -170.2415) -> (-4, -170.2415)
  line L6 (0, -177.3169) -> (0, -171.0415)
  line L7 (-2, -171.0415) -> (2, -171.0415)
  arc A1 centre (0, -173.1415) radius 2.9 clockwise from (-2, -171.0415) to (2, -171.0415)
  point P9 (0, -171.0415)
  point P6 (0, -173.1415)
  point P11 (2, -171.0415)
  point P12 (-2, -171.0415)
  horizontal L5
  tangent L5 A1
  midpoint L3 P9
  perpendicular L3 L6
  coincident P6 L6
  coincident L3 P11
  coincident L3 P12
  dimension "d833" distance L3 L5 = 0.8
  dimension "d834" distance P11 P12 = 4
extrude "Extrude14" cut sketch "floor plate retainer cut" profile of L3 A1 against normal blind 8
external_derived "ExternalDerived1"
move "Move6"
sketch "matchingFloorPlate" plane through (0, 0, 0) normal (0, 1, 0) x axis (1, 0, 0)
  line L1 (-11, 35.6) -> (-11, 0)
  line L2 (0, 57.9) -> (0, 0)
  line L3 (-4, 57.9) -> (0, 57.9)
  line L4 (-8, 44.9274) -> (-8, 53.9)
  line L5 (0, 57.9) -> (0, 0)
  line L6 (11, 0) -> (0, 0)
  line L7 (11, 35.6) -> (11, 0)
  line L8 (8, 44.9274) -> (8, 53.9)
  line L9 (4, 57.9) -> (0, 57.9)
  line L10 (-11, 0) -> (0, 0)
  line L11 (-0.5, 57.4) -> (-0.5, 0.5)
  line L12 (-4, 57.4) -> (-0.5, 57.4)
  line L13 (-7.5, 44.9274) -> (-7.5, 53.9)
  line L14 (-10.5, 35.6) -> (-10.5, 5.5)
  line L15 (-5.5, 0.5) -> (-0.5, 0.5)
  line L16 (0.5, 57.4) -> (0.5, 0.5)
  line L17 (4, 57.4) -> (0.5, 57.4)
  line L18 (7.5, 44.9274) -> (7.5, 53.9)
  line L19 (10.5, 35.6) -> (10.5, 5.5)
  line L20 (5.5, 0.5) -> (0.5, 0.5)
  line L21 (-0.5, 57.4) -> (0.5, 57.4)
  line L22 (-0.5, 0.5) -> (0.5, 0.5)
  line L23 (2.5, 26.03) -> (-2.5, 26.03)
  line L24 (4, 31.33) -> (4, 27.53)
  line L25 (-2.5, 32.83) -> (2.5, 32.83)
  line L26 (-4, 27.53) -> (-4, 31.33)
  arc A1 centre (2, 35.6) radius 13 clockwise from (-11, 35.6) to (-8.5625, 43.1785)
  arc A2 centre (-4, 53.9) radius 4 clockwise from (-8, 53.9) to (-4, 57.9)
  arc A3 centre (-11, 44.9274) radius 3 clockwise from (-8, 44.9274) to (-8.5625, 43.1785)
  arc A4 centre (-2, 35.6) radius 13 clockwise from (8.5625, 43.1785) to (11, 35.6)
  arc A5 centre (11, 44.9274) radius 3 clockwise from (8.5625, 43.1785) to (8, 44.9274)
  arc A6 centre (4, 53.9) radius 4 clockwise from (4, 57.9) to (8, 53.9)
  arc A7 centre (-4, 53.9) radius 3.5 clockwise from (-7.5, 53.9) to (-4, 57.4)
  arc A8 centre (-11, 44.9274) radius 3.5 clockwise from (-7.5, 44.9274) to (-8.1562, 42.887)
  arc A9 centre (2, 35.6) radius 12.5 clockwise from (-10.5, 35.6) to (-8.1562, 42.887)
  arc A10 centre (4, 53.9) radius 3.5 clockwise from (4, 57.4) to (7.5, 53.9)
  arc A11 centre (11, 44.9274) radius 3.5 clockwise from (8.1563, 42.887) to (7.5, 44.9274)
  arc A12 centre (-2, 35.6) radius 12.5 clockwise from (8.1563, 42.887) to (10.5, 35.6)
  arc A13 centre (5.5, 5.5) radius 5 clockwise from (10.5, 5.5) to (5.5, 0.5)
  arc A14 centre (-5.5, 5.5) radius 5 clockwise from (-5.5, 0.5) to (-10.5, 5.5)
  arc A15 centre (2.5, 31.33) radius 1.5 clockwise from (2.5, 32.83) to (4, 31.33)
  arc A16 centre (-2.5, 31.33) radius 1.5 clockwise from (-4, 31.33) to (-2.5, 32.83)
  arc A17 centre (-2.5, 27.53) radius 1.5 clockwise from (-2.5, 26.03) to (-4, 27.53)
  arc A18 centre (2.5, 27.53) radius 1.5 clockwise from (4, 27.53) to (2.5, 26.03)
  point P54 (4, 32.83)
  point P52 (-4, 26.03)
  point P53 (4, 26.03)
  concentric A6 A10
  concentric A5 A11
  concentric A4 A12
  tangent L18 A11
  tangent L17 A10
  tangent A10 L18
  tangent A12 L19
  tangent A11 A12
  tangent L19 A13
  tangent L20 A13
  concentric A2 A7
  concentric A3 A8
  concentric A1 A9
  tangent L13 A8
  tangent L12 A7
  tangent A9 L14
  tangent A7 L13
  tangent A8 A9
  tangent L14 A14
  tangent L15 A14
  equal A13 A14
  horizontal L23
  vertical L24
  horizontal L25
  vertical L26
  coincident P54 L24
  coincident P54 L25
  tangent L24 A15
  tangent L25 A15
  tangent L25 A16
  tangent L26 A16
  equal A15 A16
  coincident P52 L23
  coincident P52 L26
  tangent L23 A17
  tangent L26 A17
  equal A15 A17
  coincident P53 L23
  coincident P53 L24
  tangent L23 A18
  tangent L24 A18
  equal A15 A18
  dimension "d862" radius A13 = 5
  dimension "d865" distance L20 L23 = 25.53
  dimension "d866" distance P52 P53 = 8
  dimension "d867" distance P53 P54 = 6.8
  dimension "d868" distance L5 P53 = 4 (= "d866 / 2")
  dimension "d869" radius A15 = 1.5
extrude "Extrude1" new body sketch "matchingFloorPlate" profile of L2 L5 L12 L14 L15 A8 L13 L11 A9 A7 A12 A11 A10 L18 L20 L19 L17 L16 L21 L22 A13 A14 L23 L24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 along normal blind 4
sketch "SpringRetention" plane through (0, 4, 0) normal (0, 1, 0) x axis (1, 0, 0)
  line L1 (5.1, 26.2) -> (-5.1, 26.2)
  line L2 (5.1, 23.2) -> (5.1, 26.2)
  line L3 (-5.1, 23.2) -> (5.1, 23.2)
  line L4 (-5.1, 26.2) -> (-5.1, 23.2)
  line L5 (1.5, 6.7) -> (-1.5, 6.7)
  line L6 (1.5, 42.8) -> (1.5, 6.7)
  line L7 (-1.5, 42.8) -> (1.5, 42.8)
  line L8 (-1.5, 6.7) -> (-1.5, 42.8)
  line L9 (5.5, 0.5) -> (0.5, 0.5)
  line L10 (-10.5, 5.5) -> (-10.5, 35.6)
  line L11 (5.5, 0.5) -> (-5.5, 0.5)
  line L12 (10.5, 35.6) -> (10.5, 5.5)
  line L13 (7.5, 53.9) -> (7.5, 44.9274)
  line L14 (-4, 57.4) -> (4, 57.4)
  line L15 (-7.5, 44.9274) -> (-7.5, 53.9)
  line L16 (0, 0.5) -> (0, 57.4)
  line L17 (8.1, 23.2) -> (8.1, 26.2)
  line L18 (-8.1, 26.2) -> (-8.1, 23.2)
  line L19 (2.5, 2.7) -> (-2.5, 2.7)
  line L20 (2.5, 43.8) -> (2.5, 2.7)
  line L21 (-2.5, 2.7) -> (-2.5, 43.8)
  line L22 (5.1, 26.2) -> (8.1, 26.2)
  line L23 (5.1, 23.2) -> (8.1, 23.2)
  line L24 (-5.1, 23.2) -> (-8.1, 23.2)
  line L25 (-5.1, 26.2) -> (-8.1, 26.2)
  line L26 (-2.5, 43.8) -> (2.5, 43.8)
  arc A1 centre (2, 35.6) radius 12.5 clockwise from (-10.5, 35.6) to (-8.1562, 42.887)
  arc A2 centre (-5.5, 5.5) radius 5 clockwise from (-5.5, 0.5) to (-10.5, 5.5)
  arc A3 centre (5.5, 5.5) radius 5 clockwise from (10.5, 5.5) to (5.5, 0.5)
  arc A4 centre (-2, 35.6) radius 12.5 clockwise from (8.1562, 42.887) to (10.5, 35.6)
  arc A5 centre (11, 44.9274) radius 3.5 clockwise from (8.1562, 42.887) to (7.5, 44.9274)
  arc A6 centre (4, 53.9) radius 3.5 clockwise from (4, 57.4) to (7.5, 53.9)
  arc A7 centre (-4, 53.9) radius 3.5 clockwise from (-7.5, 53.9) to (-4, 57.4)
  arc A8 centre (-11, 44.9274) radius 3.5 clockwise from (-7.5, 44.9274) to (-8.1562, 42.887)
  point P34 (0, 57.4)
  point P35 (0, 0.5)
  point P41 (2.5, 2.7)
  point P42 (2.5, 2.7)
  point P40 (-2.5, 2.7)
  point P45 (-2.5, 2.7)
  point P44 (-2.5, 43.8)
  point P47 (-2.5, 43.8)
  point P43 (2.5, 43.8)
  point P46 (2.5, 43.8)
  point P7 (1.5, 6.7)
  point P8 (1.5, 42.8)
  point P6 (-1.5, 6.7)
  point P3 (5.1, 26.2)
  point P4 (5.1, 23.2)
  point P5 (-5.1, 23.2)
  horizontal L1
  vertical L2
  horizontal L3
  vertical L4
  horizontal L5
  vertical L6
  horizontal L7
  vertical L8
  midpoint L14 P34
  midpoint L11 P35
  perpendicular L2 L22
  perpendicular L2 L23
  perpendicular L4 L24
  perpendicular L4 L25
  coincident P41 P42
  coincident P40 P45
  coincident P44 P47
  coincident P43 P46
  dimension "d870" distance P7 P8 = 36.1
  dimension "d871" distance P6 P7 = 3
  dimension "d872" distance P3 P4 = 3
  dimension "d873" distance P4 P5 = 10.2
  dimension "d875" distance L3 L5 = 16.5
  dimension "d876" distance L5 L9 = 6.2
  dimension "d877" distance L6 L16 = 1.5 (= "d872 / 2")
  dimension "d878" distance L2 L16 = 5.1 (= "d873 / 2")
  dimension "d881" distance L2 = -3
  dimension "d882" distance L4 = -3
  dimension "d883" = 4
  dimension "d884" = 1
  dimension "d885" = 1
  dimension "d886" = 1
derived_base_feature "Derived Base Feature1" bodies "true rear lock lug"
move "Move1"
move "Move2" TranslateX 0 TranslateY 0 TranslateZ 0.9
base_mesh_feature "Base Mesh Feature"
convert_mesh "Convert Mesh" bodies "MagpulFollower_223556", "MagpulFollower_223556 (1)", "MagpulFollower_223556 (2)", "MagpulFollower_223556 (3)", "MagpulFollower_223556 (4)"
sketch "follower top profile" plane through (0, 0, 0) normal (0, 1, 0) x axis (1, 0, 0)
  line L1 (10.25, 35.6) -> (10.25, 3.75)
  line L2 (7.25, 44.9274) -> (7.25, 53.9)
  line L3 (4, 57.15) -> (0, 57.15)
  line L4 (-4, 57.15) -> (0, 57.15)
  line L5 (-7.25, 44.9274) -> (-7.25, 53.9)
  line L6 (-10.25, 35.6) -> (-10.25, 3.75)
  line L7 (-7.25, 0.75) -> (0, 0.75)
  line L8 (7.25, 0.75) -> (0, 0.75)
  line L9 (-6.25, 21.8222) -> (6.25, 21.8222)
  line L10 (0, 4.25) -> (0, 41.25)
  line L11 (0, 0) -> (0, 4.25)
  line L12 (-6.25, 12.5809) -> (-6.25, 36.0809)
  line L13 (6.25, 36.0809) -> (6.25, 12.5809)
  line L14 (0, 12.5809) -> (0, 36.0809)
  line L15 (-6.25, 12.5809) -> (6.25, 12.5809)
  line L16 (6.2187, 35.4561) -> (-6.2187, 35.4561)
  line L17 (-6.435, 13.5809) -> (6.065, 13.5809)
  line L18 (6.25, 34.4561) -> (-6.25, 34.4561)
  line L19 (-4.25, 12.5809) -> (-4.25, 36.0809)
  line L20 (4.25, 36.0809) -> (4.25, 12.5809)
  line L21 (-7.25, 2.55) -> (0, 2.55)
  line L22 (-8.45, 35.6) -> (-8.45, 3.75)
  line L23 (-5.45, 44.9274) -> (-5.45, 53.9)
  line L24 (-4, 55.35) -> (0, 55.35)
  line L25 (4, 55.35) -> (0, 55.35)
  line L26 (5.45, 44.9274) -> (5.45, 53.9)
  line L27 (8.45, 35.6) -> (8.45, 3.75)
  line L28 (7.25, 2.55) -> (0, 2.55)
  line L29 (-8.45, 8.75) -> (-10.25, 8.75)
  line L30 (10.25, 8.75) -> (8.45, 8.75)
  line L31 (-7.25, 46.15) -> (-5.45, 46.15)
  line L32 (7.25, 46.15) -> (5.45, 46.15)
  line L33 (11, 0) -> (0, 0)
  line L34 (-11, 0) -> (0, 0)
  line L35 (-1.5, 26.4309) -> (1.5, 26.4309)
  line L36 (-1.5, 20.5509) -> (-1.5, 26.4309)
  line L37 (1.5, 20.5509) -> (-1.5, 20.5509)
  line L38 (1.5, 26.4309) -> (1.5, 20.5509)
  line L39 (0, 20.5509) -> (0, 26.4309)
  line L40 (-1.5, 23.9309) -> (1.5, 23.9309)
  line L41 (-1.5, 18.0509) -> (-1.5, 20.5509)
  line L42 (1.5, 18.0509) -> (-1.5, 18.0509)
  line L43 (1.5, 20.5509) -> (1.5, 18.0509)
  line L44 (-2.4679, 4.7609) -> (1.7552, 4.7609)
  line L45 (0, 1.2302) -> (0, 0)
  line L46 (-8.45, 6.25) -> (8.45, 6.25)
  line L47 (-1.85, 3.3229) -> (1.85, 3.3229)
  line L48 (-1.85, 4.9829) -> (-1.85, 3.3229)
  line L49 (-0.6223, 4.8) -> (-0.6223, 4.6416)
  line L50 (1.85, 4.9829) -> (1.85, 3.3229)
  line L51 (5.45, 48.15) -> (-5.45, 48.15)
  line L52 (-3.9765, 37.5809) -> (3.9765, 37.5809)
  arc A1 centre (-2, 35.6) radius 12.25 clockwise from (7.9531, 42.7413) to (10.25, 35.6)
  arc A2 centre (11, 44.9274) radius 3.75 clockwise from (7.9531, 42.7413) to (7.25, 44.9274)
  arc A3 centre (4, 53.9) radius 3.25 clockwise from (4, 57.15) to (7.25, 53.9)
  arc A4 centre (-4, 53.9) radius 3.25 clockwise from (-7.25, 53.9) to (-4, 57.15)
  arc A5 centre (-11, 44.9274) radius 3.75 clockwise from (-7.25, 44.9274) to (-7.9531, 42.7413)
  arc A6 centre (2, 35.6) radius 12.25 clockwise from (-10.25, 35.6) to (-7.9531, 42.7413)
  arc A7 centre (7.25, 3.75) radius 3 clockwise from (10.25, 3.75) to (7.25, 0.75)
  arc A8 centre (-7.25, 3.75) radius 3 clockwise from (-7.25, 0.75) to (-10.25, 3.75)
  arc A9 centre (0, 12.5809) radius 6.25 clockwise from (6.25, 12.5809) to (-6.25, 12.5809)
  arc A10 centre (0, 36.0809) radius 6.25 clockwise from (-6.25, 36.0809) to (6.25, 36.0809)
  arc A11 centre (0, 36.0809) radius 4.25 clockwise from (-4.25, 36.0809) to (4.25, 36.0809)
  arc A12 centre (0, 12.5809) radius 4.25 clockwise from (4.25, 12.5809) to (-4.25, 12.5809)
  arc A13 centre (-7.25, 3.75) radius 1.2 clockwise from (-7.25, 2.55) to (-8.45, 3.75)
  arc A14 centre (2, 35.6) radius 10.45 clockwise from (-8.45, 35.6) to (-6.4906, 41.6919)
  arc A15 centre (-11, 44.9274) radius 5.55 clockwise from (-5.45, 44.9274) to (-6.4906, 41.6919)
  arc A16 centre (-4, 53.9) radius 1.45 clockwise from (-5.45, 53.9) to (-4, 55.35)
  arc A17 centre (4, 53.9) radius 1.45 clockwise from (4, 55.35) to (5.45, 53.9)
  arc A18 centre (11, 44.9274) radius 5.55 clockwise from (6.4906, 41.6919) to (5.45, 44.9274)
  arc A19 centre (-2, 35.6) radius 10.45 clockwise from (6.4906, 41.6919) to (8.45, 35.6)
  arc A20 centre (7.25, 3.75) radius 1.2 clockwise from (8.45, 3.75) to (7.25, 2.55)
  arc A21 centre (0, 12.5809) radius 7.82 clockwise from (4.5904, 6.25) to (1.85, 4.9829)
  arc A22 centre (0, 12.5809) radius 7.82 clockwise from (-1.85, 4.9829) to (-4.5904, 6.25)
  point P37 (0, 12.5809)
  point P38 (-6.2187, 35.4561)
  point P39 (6.2187, 35.4561)
  point P42 (-6.25, 34.4561)
  point P43 (6.25, 34.4561)
  point P74 (-10.25, 8.75)
  point P75 (-8.45, 8.75)
  point P76 (8.45, 8.75)
  point P77 (10.25, 8.75)
  point P78 (-5.45, 46.15)
  point P79 (-7.25, 46.15)
  point P80 (5.45, 46.15)
  point P81 (7.25, 46.15)
  point P90 (0, 26.4309)
  point P91 (0, 20.5509)
  point P92 (1.5, 23.9309)
  point P93 (-1.5, 23.9309)
  point P84 (0, 0)
  point P99 (0, 0)
  point P101 (8.45, 6.25)
  point P102 (-8.45, 6.25)
  point P103 (-4.5904, 6.25)
  point P104 (4.5904, 6.25)
  point P110 (1.85, 4.9829)
  point P112 (-5.45, 48.15)
  point P113 (5.45, 48.15)
  point P114 (3.9765, 37.5809)
  point P115 (-3.9765, 37.5809)
  point P26 (6.25, 21.8222)
  point P27 (-6.25, 21.8222)
  point P30 (0, 0)
  point P88 (-1.5, 20.5509)
  point P89 (1.5, 20.5509)
  point P94 (-1.5, 18.0509)
  point P105 (1.85, 3.3229)
  point P106 (-1.85, 3.3229)
  point P107 (-1.85, 4.9829)
  point P36 (0, 36.0809)
  point P44 (0, 36.0809)
  point P87 (-1.5, 26.4309)
  tangent A6 L6
  tangent L5 A5
  tangent A4 L5
  tangent L4 A4
  tangent L1 A1
  tangent A5 A6
  tangent L2 A3
  tangent A2 L2
  tangent A1 A2
  tangent A3 L3
  tangent L1 A7
  tangent L8 A7
  tangent L6 A8
  tangent L7 A8
  equal A7 A8
  vertical L10
  tangent L12 A9
  tangent A9 L13
  parallel L12 L13
  tangent L13 A10
  tangent L12 A10
  coincident L10 P37
  parallel L10 L14
  coincident A10 P38
  coincident A10 P39
  perpendicular L12 L16
  coincident L12 P42
  coincident L13 P43
  coincident L6 P74
  coincident L22 P75
  perpendicular L22 L29
  coincident L27 P76
  coincident L1 P77
  perpendicular L1 L30
  coincident L23 P78
  coincident L5 P79
  perpendicular L5 L31
  coincident L26 P80
  coincident L2 P81
  perpendicular L2 L32
  horizontal L35
  vertical L36
  horizontal L37
  vertical L38
  midpoint L35 P90
  midpoint L37 P91
  collinear L14 L39
  coincident L38 P92
  coincident L36 P93
  perpendicular L36 L40
  horizontal L8
  horizontal L7
  perpendicular L37 L41
  vertical L43
  horizontal L42
  horizontal L44
  tangent L44 A22
  coincident P84 P99
  perpendicular L34 L45
  collinear L11 L45
  coincident L27 P101
  coincident L22 P102
  perpendicular L22 L46
  concentric A9 A22
  coincident L46 P103
  coincident L46 P104
  horizontal L47
  perpendicular L44 L48
  perpendicular L44 L49
  coincident P110 A22
  perpendicular L47 L50
  concentric A21 A22
  coincident L23 P112
  coincident L26 P113
  perpendicular L26 L51
  coincident A11 P114
  coincident A11 P115
  horizontal L52
  dimension "d895" radius A7 = 3
  dimension "d938" distance P26 P27 = 12.5
  dimension "d943" distance P27 L10 = 6.25 (= "d938 / 2")
  dimension "d947" radius A9 = 6.25 (= "d938 / 2")
  dimension "d958" = 1
  dimension "d959" = 1
  dimension "d960" = -2
  dimension "d966" = -1.8
  dimension "d967" distance L7 L29 = 8
  dimension "d968" distance L8 L30 = 8 (= "d967")
  dimension "d969" distance L4 L31 = 11
  dimension "d970" distance L3 L32 = 11 (= "d969")
  dimension "d1005" distance L7 P37 = 11.8309
  dimension "d1006" distance P30 P37 = 12.5809
  dimension "d1008" distance P88 P89 = 3
  dimension "d1010" distance L35 L40 = 2.5
  dimension "d1011" distance L7 L34 = 0.75
  dimension "d1012" distance P88 P94 = 2.5
  dimension "d1016" distance L37 L40 = 3.38
  dimension "d1018" distance L8 L46 = 5.5
  dimension "d1019" distance P105 P106 = 3.7
  dimension "d1020" distance L11 P106 = 1.85 (= "d1019 / 2")
  dimension "d1021" distance P106 P107 = 1.66
  dimension "d1022" distance L31 L51 = 2
  dimension "d1034" distance P36 L52 = 1.5
  dimension "d1099" distance P44 P87 = 9.65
